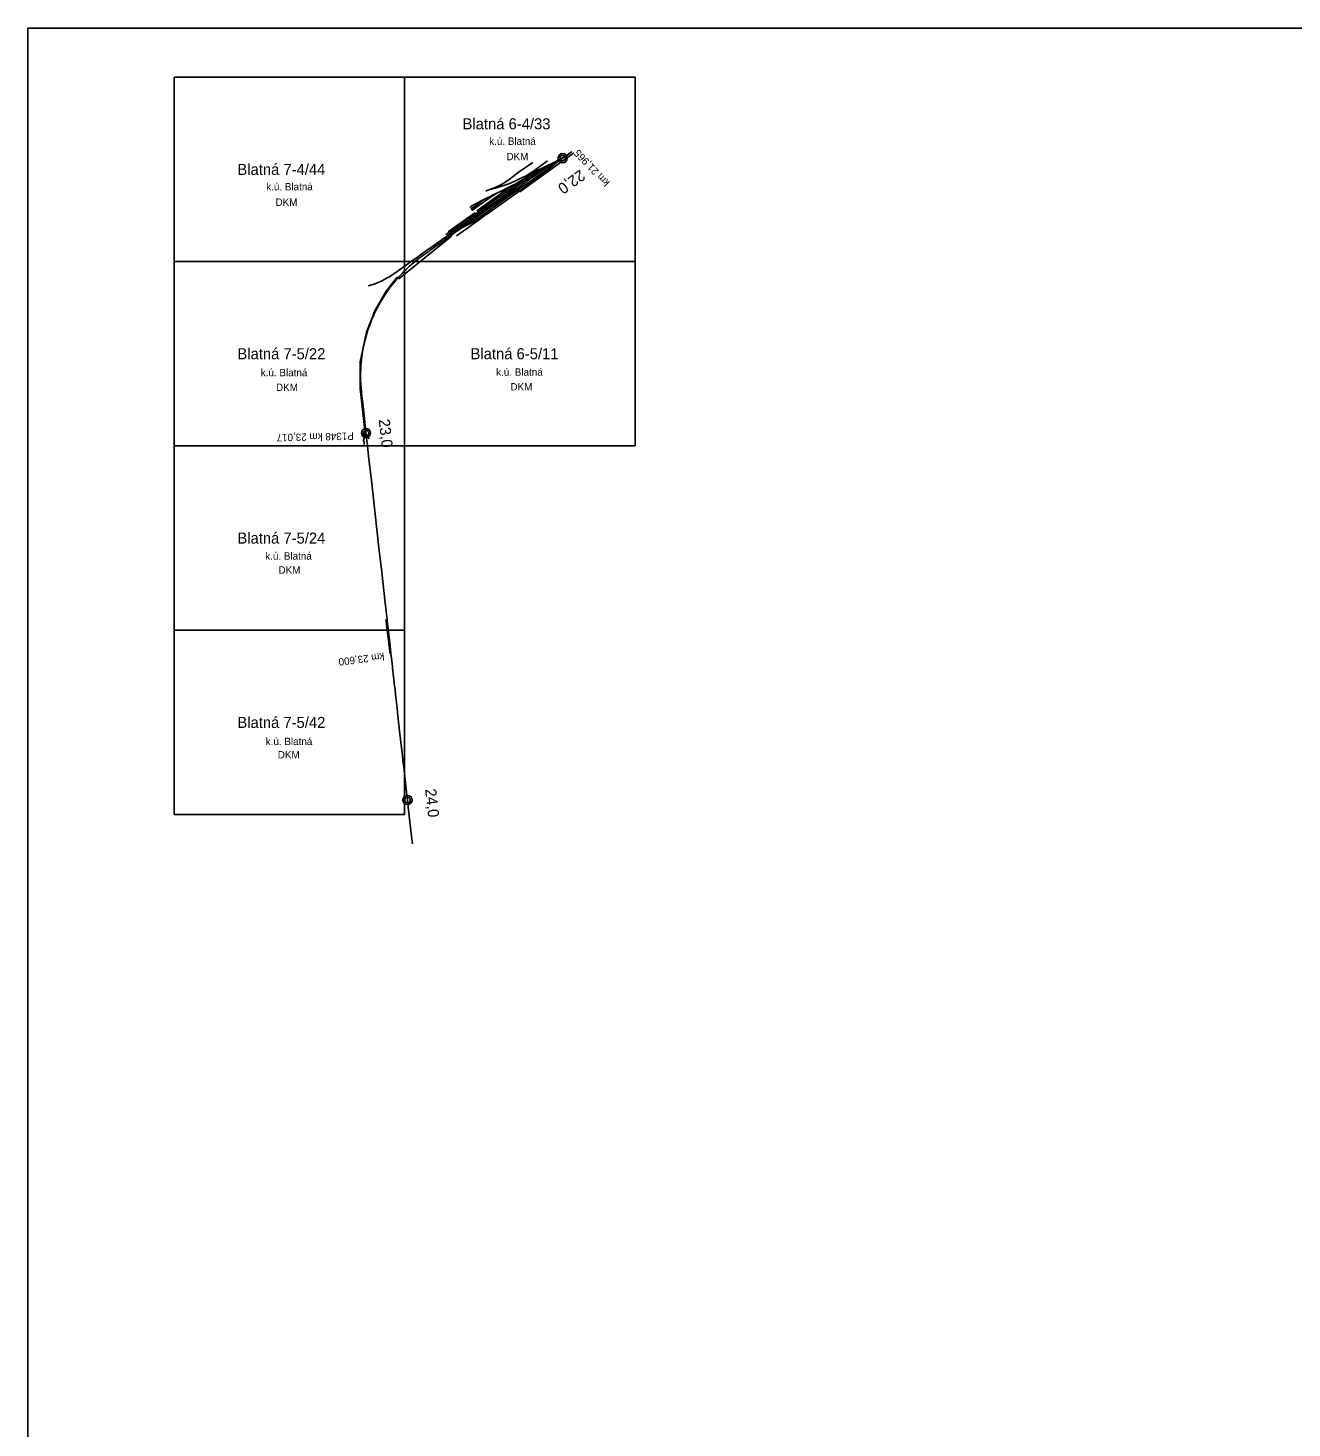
# Model space of a CAD drawing. Extents: x -793522 to -786663, y -1118682 to -1109366.
# Drawn here: x -793522 to -790093, y -1113164 to -1109366 of the extents above; entities that cross this region are included whole.
import ezdxf

# ---------------------------------------------------------------- set-up
doc = ezdxf.new("R2010")
doc.units = 0
doc.layers.add('Vrstva 1', color=7, linetype='Continuous')
doc.layers.add('Vrstva 5', color=7, linetype='Continuous')

msp = doc.modelspace()

# ---------------------------------------------------------------- linework, layer by layer
at = {"layer": 'Vrstva 1'}
for p, q in [((-792500, -1109500), (-793125, -1109500)), ((-793125, -1109500), (-793125, -1110000)), ((-791875, -1109500), (-792500, -1109500)), ((-792500, -1109500), (-792500, -1110000)), ((-792500, -1110000), (-792500, -1109500)), ((-791875, -1110000), (-791875, -1109500)), ((-792041.13, -1109704.75), (-792187.76, -1109811.11)), ((-792196.9, -1109800.79), (-792303.98, -1109875.73)), ((-792187.76, -1109811.11), (-792196.9, -1109800.79)), ((-792309.37, -1109867.98), (-792381.88, -1109919.59)), ((-792303.98, -1109875.73), (-792309.37, -1109867.98)), ((-792381.88, -1109919.59), (-792373.33, -1109931.54)), ((-792373.33, -1109931.54), (-792515.55, -1110046.71)), ((-792500, -1110000), (-793125, -1110000)), ((-793125, -1110000), (-793125, -1110500)), ((-793125, -1110000), (-792500, -1110000)), ((-792500, -1110000), (-791875, -1110000)), ((-791875, -1110000), (-792500, -1110000)), ((-792500, -1110000), (-792500, -1110500)), ((-792500, -1110500), (-792500, -1110000)), ((-791875, -1110500), (-791875, -1110000)), ((-792520.18, -1110042.35), (-792549.85, -1110079.92)), ((-792515.55, -1110046.71), (-792520.18, -1110042.35)), ((-792549.85, -1110079.92), (-792580.35, -1110131.61)), ((-792580.35, -1110131.61), (-792603.71, -1110191.71)), ((-792603.71, -1110191.71), (-792620.65, -1110272.28)), ((-792620.65, -1110272.28), (-792620.63, -1110343.84)), ((-792620.63, -1110343.84), (-792612.68, -1110417.17)), ((-792612.68, -1110417.17), (-792606.1, -1110475.59)), ((-792608.35, -1110474.43), (-792612.54, -1110486.17)), ((-792612.54, -1110486.17), (-792609.77, -1110488.09)), ((-792609.77, -1110488.09), (-792610.09, -1110495.99)), ((-792606.1, -1110475.59), (-792608.35, -1110474.43)), ((-792606.1, -1110475.59), (-792601.71, -1110474.49)), ((-792601.71, -1110474.49), (-792596.44, -1110480.58)), ((-793125, -1110500), (-792500, -1110500)), ((-792500, -1110500), (-793125, -1110500)), ((-793125, -1110500), (-793125, -1111000)), ((-792500, -1110500), (-791875, -1110500)), ((-792500, -1111000), (-792500, -1110500)), ((-792551.43, -1110970.53), (-792539.2, -1111063.62)), ((-793125, -1111000), (-792500, -1111000)), ((-792500, -1111000), (-793125, -1111000)), ((-793125, -1111000), (-793125, -1111500)), ((-792500, -1111500), (-792500, -1111000)), ((-793125, -1111500), (-792500, -1111500))]:
    msp.add_line(p, q, dxfattribs=at)
at = {"layer": 'Vrstva 5'}
for p, q in [((-792152.172, -1109731.189), (-792164.136, -1109739.571)), ((-792102.917, -1109735.086), (-792106.473, -1109736.785)), ((-792076.704, -1109721.077), (-792080.612, -1109723.386)), ((-792157.36, -1109761.008), (-792159.058, -1109761.822)), ((-792130.401, -1109748.193), (-792132.918, -1109749.414)), ((-792222.678, -1109801.334), (-792234.617, -1109807.295)), ((-792189.968, -1109786.245), (-792215.685, -1109804.674)), ((-792191.672, -1109785.069), (-792198.675, -1109788.867)), ((-792233.239, -1109840.497), (-792274.845, -1109870.124)), ((-792264.443, -1109821.873), (-792270.145, -1109824.644)), ((-792296.791, -1109885.756), (-792332.444, -1109911.057)), ((-792298.563, -1109884.616), (-792310.775, -1109891.358)), ((-792351.013, -1109908.988), (-792358.278, -1109915.512)), ((-792333.184, -1109902.524), (-792334.933, -1109903.379)), ((-792518.225, -1111231.772), (-792515.366, -1111257.419)), ((-792515.366, -1111257.419), (-792514.917, -1111261.404)), ((-792514.917, -1111261.404), (-792514.471, -1111265.375)), ((-792509.253, -1111311.424), (-792507.031, -1111331.048)), ((-792502.439, -1111371.634), (-792501.402, -1111380.746)), ((-792494.833, -1111438.97), (-792492.371, -1111460.496))]:
    msp.add_line(p, q, dxfattribs=at)
msp.add_lwpolyline([(-793521.92, -1109366.5), (-786663.17, -1109366.5), (-786663.17, -1118682.04), (-793521.92, -1118682.04)], close=True, dxfattribs=at)
for points in [[(-792112.367, -1109727.152), (-792136.086, -1109744.115), (-792147.005, -1109751.93), (-792158.087, -1109759.205), (-792159.864, -1109760.345)], [(-792080.612, -1109723.386), (-792081.693, -1109724.018), (-792091.469, -1109729.801), (-792102.917, -1109735.086), (-792106.473, -1109736.785), (-792107.219, -1109737.137), (-792114.337, -1109740.534), (-792130.401, -1109748.193)], [(-792075.695, -1109722.584), (-792077.009, -1109723.523), (-792089.239, -1109732.208), (-792102.812, -1109741.854)], [(-792081.693, -1109724.018), (-792091.469, -1109729.801), (-792102.084, -1109736.536)], [(-792075.695, -1109722.584), (-792077.009, -1109723.523), (-792089.239, -1109732.208), (-792101.657, -1109743.277)], [(-792048.298, -1109703.112), (-792049.603, -1109704.038), (-792059.39, -1109710.995), (-792076.704, -1109721.077)], [(-792048.298, -1109703.112), (-792049.603, -1109704.038), (-792059.39, -1109710.995), (-792075.695, -1109722.584)], [(-792046.397, -1109701.769), (-792048.298, -1109703.112)], [(-792181.825, -1109772.709), (-792192.242, -1109777.756), (-792202.932, -1109782.847), (-792217.538, -1109789.286), (-792230.614, -1109793.941), (-792254.249, -1109800.789)], [(-792164.136, -1109739.571), (-792188.377, -1109755.967), (-792204.665, -1109768.797), (-792216.303, -1109777.779), (-792228.006, -1109785.677), (-792240.498, -1109792.677), (-792254.122, -1109798.753)], [(-792102.812, -1109741.854), (-792123.667, -1109756.658), (-792129.568, -1109760.851), (-792148.095, -1109774.021), (-792149.772, -1109775.22), (-792176.618, -1109794.297), (-792178.279, -1109795.482), (-792235.955, -1109836.569)], [(-792101.657, -1109743.277), (-792112.226, -1109752.612), (-792119.363, -1109758.656), (-792120.022, -1109759.185), (-792143.827, -1109776.793), (-792148.785, -1109780.33), (-792173.729, -1109798.13), (-792174.993, -1109799.022), (-792192.819, -1109811.735), (-792233.239, -1109840.497)], [(-792130.168, -1109750.232), (-792139.498, -1109756.34), (-792153.895, -1109766.478), (-792155.549, -1109767.654), (-792156.934, -1109768.632), (-792199.096, -1109798.654), (-792200.731, -1109799.821), (-792212.815, -1109808.399)], [(-792102.084, -1109736.536), (-792113.19, -1109743.784), (-792126.569, -1109752.931), (-792133.591, -1109757.916), (-792151.009, -1109770.316), (-792152.701, -1109771.516), (-792179.337, -1109790.454), (-792181.061, -1109791.691), (-792209.964, -1109812.253)], [(-792168.009, -1109770.373), (-792176.537, -1109776.537), (-792191.672, -1109785.069)], [(-792168.009, -1109770.373), (-792176.537, -1109776.537), (-792189.968, -1109786.245)], [(-792159.864, -1109760.345), (-792170.449, -1109767.269), (-792181.825, -1109772.709)], [(-792159.058, -1109761.822), (-792170.449, -1109767.269), (-792180.682, -1109772.162), (-792181.825, -1109772.709)], [(-792156.693, -1109762.855), (-792157.857, -1109763.595), (-792160.216, -1109765.116), (-792168.009, -1109770.373)], [(-792132.918, -1109749.414), (-792133.685, -1109749.792), (-792140.789, -1109753.148), (-792146.781, -1109755.983), (-792157.36, -1109761.008)], [(-792132.918, -1109749.414), (-792133.685, -1109749.792), (-792140.789, -1109753.148), (-792156.693, -1109762.855)], [(-792106.473, -1109736.785), (-792107.219, -1109737.137), (-792114.337, -1109740.534), (-792130.168, -1109750.232)], [(-792215.685, -1109804.674), (-792243.721, -1109824.637), (-792285.256, -1109854.192), (-792301.393, -1109865.673), (-792340.233, -1109893.305)], [(-792212.815, -1109808.399), (-792241.248, -1109828.653), (-792282.655, -1109858.154), (-792308.024, -1109876.216), (-792322.953, -1109886.791), (-792325.412, -1109888.536)], [(-792222.383, -1109803.378), (-792246.597, -1109820.677), (-792270.21, -1109837.668), (-792304.068, -1109862.007)], [(-792254.122, -1109798.753), (-792271.172, -1109805.601), (-792279.012, -1109807.83), (-792279.552, -1109807.984)], [(-792254.249, -1109800.789), (-792271.172, -1109805.601), (-792279.012, -1109807.83), (-792279.552, -1109807.984)], [(-792234.617, -1109807.295), (-792236.049, -1109807.995), (-792249.545, -1109814.591), (-792263.137, -1109821.225), (-792264.443, -1109821.873)], [(-792234.617, -1109807.295), (-792236.049, -1109807.995), (-792249.545, -1109814.591), (-792263.552, -1109823.469)], [(-792198.675, -1109788.867), (-792206.85, -1109793.113), (-792222.678, -1109801.334)], [(-792198.675, -1109788.867), (-792206.85, -1109793.113), (-792222.383, -1109803.378)], [(-792209.964, -1109812.253), (-792238.659, -1109832.672), (-792279.729, -1109861.905), (-792304.676, -1109879.641), (-792335.484, -1109901.571)], [(-792292.85, -1109835.725), (-792295.26, -1109836.906), (-792297.092, -1109837.812), (-792310.011, -1109844.386), (-792314.682, -1109847.139), (-792323.504, -1109853.016)], [(-792292.022, -1109837.142), (-792310.514, -1109850.595), (-792320.237, -1109857.613)], [(-792263.552, -1109823.469), (-792270.577, -1109828.18), (-792289.271, -1109841.39), (-792307.709, -1109854.482), (-792317.523, -1109861.432)], [(-792235.955, -1109836.569), (-792276.654, -1109865.619), (-792288.672, -1109874.201), (-792310.787, -1109889.217)], [(-792270.145, -1109824.644), (-792271.294, -1109825.21), (-792281.477, -1109830.175), (-792292.85, -1109835.725)], [(-792270.145, -1109824.644), (-792271.294, -1109825.21), (-792281.477, -1109830.175), (-792292.022, -1109837.142)], [(-792274.845, -1109870.124), (-792276, -1109870.952), (-792282.348, -1109875.468), (-792298.563, -1109884.616)], [(-792274.845, -1109870.124), (-792276, -1109870.952), (-792282.348, -1109875.468), (-792296.791, -1109885.756)], [(-792340.233, -1109893.305), (-792363.306, -1109909.668), (-792387.967, -1109927.16)], [(-792335.484, -1109901.571), (-792350.031, -1109911.914), (-792356.412, -1109916.469), (-792357.131, -1109916.962), (-792370.675, -1109926.593), (-792382.918, -1109935.309), (-792384.216, -1109936.222)], [(-792358.278, -1109915.512), (-792365.021, -1109921.361), (-792370.675, -1109926.593), (-792382.918, -1109935.309), (-792384.216, -1109936.222)], [(-792352.161, -1109907.562), (-792360.352, -1109913.373), (-792372.746, -1109922.208), (-792382.306, -1109928.996)], [(-792332.444, -1109911.057), (-792359.633, -1109930.243)], [(-792334.933, -1109903.379), (-792350.031, -1109911.914), (-792356.412, -1109916.469), (-792357.131, -1109916.962)], [(-792325.412, -1109888.536), (-792326.364, -1109889.22), (-792338.621, -1109897.931), (-792352.161, -1109907.562)], [(-792325.412, -1109888.536), (-792326.364, -1109889.22), (-792338.621, -1109897.931), (-792351.013, -1109908.988)], [(-792310.787, -1109889.217), (-792327.489, -1109899.534), (-792332.485, -1109902.157), (-792333.184, -1109902.524)], [(-792310.775, -1109891.358), (-792323.192, -1109897.278), (-792327.489, -1109899.534), (-792332.485, -1109902.157), (-792333.184, -1109902.524)], [(-792382.306, -1109928.996), (-792388.05, -1109933.087), (-792399.543, -1109941.274), (-792417.359, -1109953.934), (-792424.864, -1109959.254), (-792436.724, -1109967.69)], [(-792384.216, -1109936.222), (-792385.228, -1109936.928), (-792396.779, -1109945.128), (-792414.588, -1109957.76), (-792422.589, -1109963.466), (-792430.839, -1109969.365)], [(-792469.28, -1109997.713), (-792480.839, -1110007.285), (-792486.668, -1110012.396), (-792487.555, -1110013.211), (-792497.161, -1110022.119), (-792502.934, -1110027.774), (-792506.241, -1110031.12), (-792520.156, -1110046.13), (-792523.847, -1110050.383), (-792534.853, -1110063.822), (-792538.946, -1110069.159), (-792547.807, -1110081.353), (-792553.262, -1110089.407), (-792566.314, -1110110.642), (-792578.125, -1110132.737), (-792582.48, -1110141.806), (-792584.962, -1110147.243), (-792588.854, -1110156.212), (-792589.022, -1110156.604), (-792590.9, -1110161.202), (-792593.033, -1110166.646), (-792596.557, -1110176.179), (-792599.508, -1110184.763), (-792606.631, -1110208.856), (-792612.179, -1110233.19), (-792616.218, -1110257.783), (-792618.746, -1110282.903), (-792619.618, -1110307.658), (-792619.453, -1110321.142), (-792618.951, -1110332.537)], [(-792436.724, -1109967.69), (-792454.579, -1109980.366), (-792465.322, -1109987.996), (-792484.841, -1110001.871), (-792502.26, -1110014.281), (-792513.727, -1110022.432)], [(-792430.839, -1109969.365), (-792433.88, -1109971.532), (-792451.751, -1109984.401), (-792460.28, -1109990.725), (-792469.28, -1109997.713)], [(-792513.727, -1110022.432), (-792521.166, -1110027.678), (-792528.457, -1110032.703), (-792529.084, -1110033.128), (-792533.559, -1110036.106), (-792538.721, -1110039.417), (-792543.373, -1110042.262), (-792545.734, -1110043.659), (-792553.524, -1110048.007), (-792561.34, -1110051.966)], [(-792561.34, -1110051.966), (-792582.592, -1110060.89), (-792598.872, -1110066.009)], [(-792618.951, -1110332.537), (-792618.134, -1110343.638), (-792617.131, -1110354.569), (-792615.984, -1110365.504), (-792614.756, -1110376.511)], [(-792614.756, -1110376.511), (-792611.021, -1110409.572), (-792610.195, -1110416.892)], [(-792610.195, -1110416.892), (-792607.94, -1110436.893), (-792604.08, -1110471.209), (-792603.386, -1110477.339), (-792602.194, -1110488.274), (-792601.806, -1110491.366), (-792596.747, -1110536.276), (-792591.137, -1110586.006), (-792585.542, -1110635.602), (-792579.987, -1110685.23), (-792574.36, -1110735.035), (-792568.75, -1110784.808), (-792563.134, -1110834.334), (-792557.474, -1110884.045), (-792551.862, -1110933.856), (-792547.779, -1110970.118), (-792546.293, -1110983.313), (-792545.099, -1110993.946), (-792544.647, -1110997.983), (-792540.666, -1111033.175), (-792537.329, -1111062.406)], [(-792537.329, -1111062.406), (-792535.028, -1111082.591), (-792533.226, -1111098.561), (-792532.78, -1111102.612), (-792530.148, -1111125.979), (-792529.407, -1111132.558), (-792528.097, -1111144.21)], [(-792528.097, -1111144.21), (-792526.124, -1111161.687), (-792523.82, -1111182.197), (-792520.497, -1111211.59), (-792518.225, -1111231.772)], [(-792514.471, -1111265.375), (-792512.667, -1111281.266), (-792509.253, -1111311.424)], [(-792507.031, -1111331.048), (-792503.688, -1111360.626), (-792502.439, -1111371.634)], [(-792501.402, -1111380.746), (-792498.721, -1111404.708), (-792495.827, -1111430.255), (-792495.781, -1111430.64), (-792494.833, -1111438.97)], [(-792492.371, -1111460.496), (-792490.128, -1111480.234), (-792487.569, -1111502.953)], [(-792487.569, -1111502.953), (-792482.99, -1111543.453), (-792481.186, -1111559.408)], [(-792481.186, -1111559.408), (-792478.904, -1111579.613)]]:
    msp.add_lwpolyline(points, dxfattribs=at)
for centre, radius in [((-792071.53, -1109719.623), 12.457), ((-792071.53, -1109719.623), 7.519), ((-792604.768, -1110465.096), 12.457), ((-792604.768, -1110465.096), 7.519), ((-792492.368, -1111460.525), 12.457), ((-792492.368, -1111460.525), 7.519)]:
    msp.add_circle(centre, radius, dxfattribs=at)

# ---------------------------------------------------------------- texts
at = {"layer": 'Vrstva 1'}
for s, height, p in [('Blatná 6-4/33', 30, (-792342.968, -1109641.36)), ('k.ú. Blatná', 20, (-792270.586, -1109683.4)), ('Blatná 7-4/44', 30, (-792953.831, -1109765)), ('DKM', 20, (-792223.794, -1109725.19)), ('k.ú. Blatná', 20, (-792875.586, -1109807.05)), ('DKM', 20, (-792850.374, -1109848.9)), ('Blatná 7-5/22', 30, (-792953.831, -1110265)), ('Blatná 6-5/11', 30, (-792321.248, -1110265)), ('k.ú. Blatná', 20, (-792890.376, -1110311.07)), ('k.ú. Blatná', 20, (-792251.766, -1110309.72)), ('DKM', 20, (-792848.984, -1110350.96)), ('DKM', 20, (-792212.994, -1110349.62)), ('Blatná 7-5/24', 30, (-792953.831, -1110765)), ('k.ú. Blatná', 20, (-792878.296, -1110808.57)), ('DKM', 20, (-792842.264, -1110846.49)), ('Blatná 7-5/42', 30, (-792953.831, -1111265)), ('k.ú. Blatná', 20, (-792876.956, -1111311.45)), ('DKM', 20, (-792844.274, -1111347.66))]:
    msp.add_text(s, height=height, dxfattribs=at).set_placement(p)
for s, rotation, p in [('km 21,965', 133.721308, (-791941.733, -1109784.452)), ('P1348 km 23,017', 181.2198, (-792638.104, -1110463.426)), ('km 23,600', 187.243506, (-792556.397, -1111060.789))]:
    msp.add_text(s, height=20, rotation=rotation, dxfattribs=at).set_placement(p)
at = {"layer": 'Vrstva 5'}
for s, height, rotation, p in [('22,0', 30, 215.403828, (-792023.825, -1109749.38)), ('23,0', 30, 276.417881, (-792570.579, -1110428.489)), ('24,0', 29.9999, 276.483203, (-792444.658, -1111431.345))]:
    msp.add_text(s, height=height, rotation=rotation, dxfattribs=at).set_placement(p)

doc.saveas('drawing.dxf')
